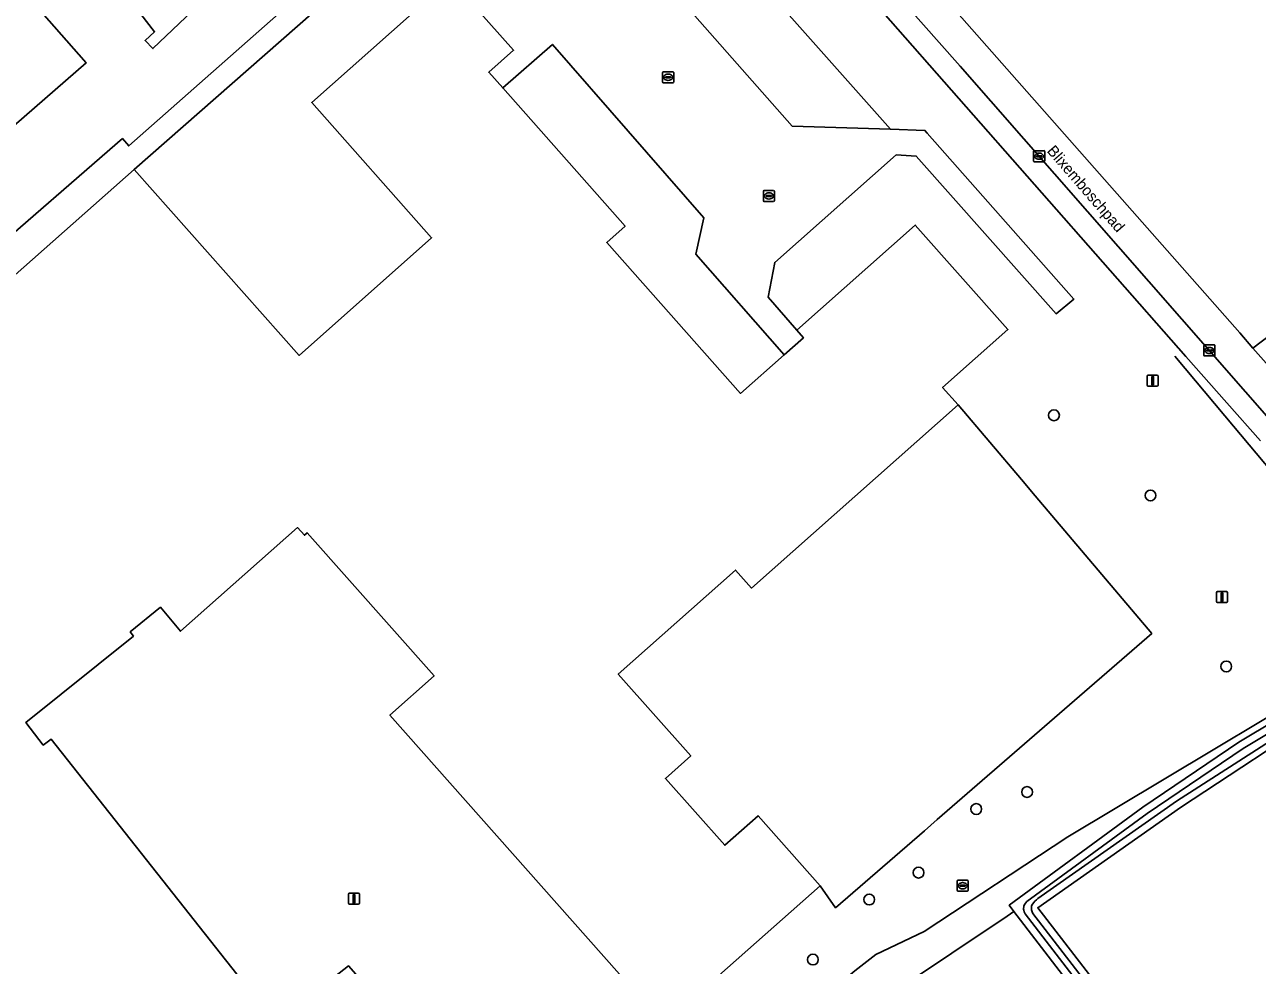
# Model space of a CAD drawing. Extents: x 159451 to 160664, y 388402 to 389723.
# Drawn here: x 159793.8 to 159905.3, y 389005.7 to 389090.8 of the extents above; entities that cross this region are included whole.
import ezdxf

# ---------------------------------------------------------------- set-up
doc = ezdxf.new("R2010")
doc.units = 0
for name, color, linetype in [('IMGEO_Boom', 7, 'Continuous'), ('IMGEO_Erf', 7, 'Continuous'), ('IMGEO_Fietspad_gesloten', 7, 'Continuous'), ('IMGEO_Greppel_droge_sloot', 7, 'Continuous'), ('IMGEO_Groenvoorziening', 7, 'Continuous'), ('IMGEO_Hek', 7, 'Continuous'), ('IMGEO_Kolk', 7, 'Continuous'), ('IMGEO_Lichtmast', 7, 'Continuous'), ('IMGEO_Loofbos', 7, 'Continuous'), ('IMGEO_Oever', 7, 'Continuous'), ('IMGEO_Openbare_ruimte_label', 7, 'Continuous'), ('IMGEO_Pand', 7, 'Continuous'), ('IMGEO_Voetpad_gesloten', 7, 'Continuous'), ('IMGEO_Voetpad_open', 7, 'Continuous')]:
    doc.layers.add(name, color=color, linetype=linetype)

msp = doc.modelspace()

# ---------------------------------------------------------------- linework, layer by layer
at = {"layer": 'IMGEO_Boom'}
for centre in [(159886.9, 389055.46), (159895.63, 389048.21), (159902.48, 389032.75), (159884.47, 389021.4), (159879.87, 389019.86), (159874.65, 389014.11), (159870.19, 389011.68), (159865.1, 389006.25)]:
    msp.add_circle(centre, 0.489, dxfattribs=at)
at = {"layer": 'IMGEO_Erf'}
for points in [[(159811.1, 389205.1), (159812.39, 389206.33), (159879.5, 389250), (159883.29, 389252.48), (159884.66, 389252.42), (159888.52, 389254.99), (159887.08, 389257.25), (159875.98, 389250), (159827.25, 389218.15), (159799.4, 389200.15), (159799.27, 389200.07), (159828.52, 389151.96), (159838.07, 389138), (159844.35, 389130.19), (159903.7, 389062.9), (159904.89, 389061.54), (159920.65, 389073.49)], [(159773.64, 388966.9), (159823.09, 389005.69), (159837.55, 388989.2), (159842.67, 388984.89), (159855.94, 388995.34), (159851.63, 389000.41), (159826.85, 389028.35), (159830.84, 389031.89), (159819.35, 389044.84), (159819.11, 389044.62), (159818.5, 389045.31), (159807.9, 389035.94), (159806.09, 389038.11), (159803.36, 389035.87), (159803.65, 389035.5), (159793.91, 389027.68), (159795.49, 389025.64), (159796.2, 389026.19), (159815.39, 389001.92), (159802.75, 388992.16), (159798.7, 388997.39), (159786.57, 388987.97)]]:
    msp.add_lwpolyline(points, dxfattribs=at)
for points in [[(159785.47, 389097.08), (159790.98, 389090.88), (159790.7, 389090.63), (159792.83, 389088.23), (159781.9, 389078.51), (159785.1, 389074.91), (159799.37, 389087.32), (159788.43, 389099.73)], [(159819.77, 389083.75), (159832.33, 389094.89), (159829.34, 389098.18), (159827.36, 389098.43), (159803.71, 389077.69), (159818.63, 389060.87), (159830.62, 389071.51)], [(159855.25, 389073.32), (159841.54, 389088.99), (159837.05, 389085.05), (159848.12, 389072.56), (159846.46, 389071.08), (159858.56, 389057.43), (159862.49, 389060.92), (159854.52, 389070.02)], [(159865.75, 389012.93), (159867.15, 389010.93), (159875.18, 389017.9), (159876.34, 389018.91), (159895.75, 389035.74), (159885.2, 389048.17), (159883.97, 389049.65), (159878.23, 389056.39), (159859.56, 389039.84), (159858.11, 389041.47), (159847.5, 389032.06), (159854.05, 389024.67), (159851.76, 389022.63), (159857.12, 389016.58), (159860.14, 389019.26)]]:
    msp.add_lwpolyline(points, close=True, dxfattribs=at)
at = {"layer": 'IMGEO_Fietspad_gesloten'}
for points in [[(159917.95, 389046.6), (159909.94, 389055.82), (159904.89, 389061.54), (159903.7, 389062.9), (159844.35, 389130.19), (159838.07, 389138), (159828.52, 389151.96), (159799.27, 389200.07), (159799.4, 389200.15)], [(159796.89, 389198.35), (159802.38, 389189.41), (159812.11, 389173.26), (159824.51, 389152.82), (159827.92, 389147.6), (159831.09, 389142.87), (159835.51, 389136.48), (159838.57, 389132.61), (159846.19, 389123.51), (159867.98, 389098.82), (159878.43, 389087.02), (159907.01, 389054.41), (159915.5, 389044.88), (159924.27, 389033.99), (159926.66, 389035.76), (159926.14, 389036.41), (159917.95, 389046.6)]]:
    msp.add_lwpolyline(points, dxfattribs=at)
at = {"layer": 'IMGEO_Greppel_droge_sloot'}
for points in [[(159913.79, 389031.18), (159904, 389025.32), (159895.33, 389019.47), (159884.45, 389011.49), (159884.33, 389011.36), (159884.2, 389011.16), (159884.17, 389011.07), (159884.15, 389010.81), (159884.17, 389010.72), (159884.22, 389010.56), (159884.29, 389010.4), (159910.13, 388976.78)], [(159911.09, 388976.57), (159884.98, 389010.41), (159884.92, 389010.58), (159884.88, 389010.76), (159884.86, 389010.93), (159884.88, 389011.1), (159884.96, 389011.26), (159885.07, 389011.41), (159885.18, 389011.54), (159885.31, 389011.66), (159885.44, 389011.78), (159897.97, 389020.57), (159911.29, 389029.1)]]:
    msp.add_lwpolyline(points, dxfattribs=at)
at = {"layer": 'IMGEO_Groenvoorziening'}
for points in [[(159905.58, 389053.15), (159902.52, 389056.6), (159898.84, 389060.77), (159850.91, 389115.22)], [(159803.08, 389093.36), (159805.56, 389090.14), (159804.71, 389089.33), (159805.41, 389088.61), (159811.96, 389094.87)], [(159862.95, 389091.64), (159872.11, 389081.32), (159875.23, 389081.22), (159875.44, 389080.98), (159888.71, 389065.96), (159887.09, 389064.64), (159874.45, 389078.9), (159872.63, 389079.01), (159861.65, 389069.28), (159861.06, 389066.14), (159863.64, 389063.15), (159874.36, 389072.66), (159882.73, 389063.22), (159876.82, 389057.98), (159878.23, 389056.39), (159883.97, 389049.65), (159885.2, 389048.17), (159895.75, 389035.74), (159876.34, 389018.91), (159875.18, 389017.9), (159867.15, 389010.93), (159865.75, 389012.93), (159851.63, 389000.41)], [(159857.74, 388993.52), (159882.68, 389010.17), (159883.27, 389010.6), (159882.85, 389011.16), (159894.94, 389020.03), (159903.63, 389025.9), (159913.46, 389031.77)]]:
    msp.add_lwpolyline(points, dxfattribs=at)
at = {"layer": 'IMGEO_Hek'}
for points in [[(159897.84, 389060.79), (159902.35, 389055.41)], [(159902.35, 389055.41), (159918.88, 389035.72), (159888.16, 389017.35), (159875.15, 389008.78), (159870.78, 389006.7), (159868.88, 389005.22), (159856.44, 388994.83)]]:
    msp.add_lwpolyline(points, dxfattribs=at)
at = {"layer": 'IMGEO_Kolk'}
for p, q in [((159851.51, 389085.59), (159851.51, 389086.44)), ((159851.58, 389086.52), (159852.43, 389086.52)), ((159852, 389086.3), (159852.02, 389086.3)), ((159852.51, 389086.44), (159852.51, 389085.59)), ((159852.43, 389085.52), (159851.58, 389085.52)), ((159851.77, 389086.01), (159851.77, 389086.02)), ((159851.81, 389086.06), (159852.21, 389086.06)), ((159852.2, 389085.97), (159851.81, 389085.97)), ((159852.02, 389085.74), (159851.99, 389085.74)), ((159852.25, 389086.02), (159852.25, 389086.01)), ((159885.06, 389078.45), (159885.06, 389079.31)), ((159885.13, 389079.38), (159885.99, 389079.38)), ((159885.32, 389078.87), (159885.32, 389078.89)), ((159885.36, 389078.92), (159885.76, 389078.92)), ((159885.76, 389078.84), (159885.36, 389078.84)), ((159885.55, 389079.16), (159885.57, 389079.16)), ((159885.57, 389078.6), (159885.55, 389078.6)), ((159885.8, 389078.89), (159885.8, 389078.87)), ((159886.06, 389079.31), (159886.06, 389078.45)), ((159885.99, 389078.38), (159885.13, 389078.38)), ((159860.62, 389074.86), (159860.62, 389075.71)), ((159860.7, 389075.79), (159861.55, 389075.79)), ((159860.88, 389075.28), (159860.88, 389075.29)), ((159861.32, 389075.24), (159860.92, 389075.24)), ((159860.93, 389075.33), (159861.32, 389075.33)), ((159861.11, 389075.57), (159861.14, 389075.57)), ((159861.37, 389075.29), (159861.37, 389075.28)), ((159861.62, 389075.71), (159861.62, 389074.86)), ((159861.55, 389074.79), (159860.7, 389074.79)), ((159861.13, 389075.01), (159861.11, 389075.01)), ((159900.45, 389060.89), (159900.45, 389061.75)), ((159900.53, 389061.82), (159901.38, 389061.82)), ((159901.45, 389061.75), (159901.45, 389060.89)), ((159901.38, 389060.82), (159900.53, 389060.82)), ((159900.71, 389061.31), (159900.71, 389061.33)), ((159900.75, 389061.36), (159901.15, 389061.36)), ((159901.15, 389061.28), (159900.75, 389061.28)), ((159900.94, 389061.6), (159900.97, 389061.6)), ((159900.96, 389061.04), (159900.94, 389061.04)), ((159901.2, 389061.33), (159901.2, 389061.31)), ((159878.15, 389012.51), (159878.15, 389013.36)), ((159878.22, 389013.44), (159879.07, 389013.44)), ((159878.41, 389012.93), (159878.41, 389012.94)), ((159878.45, 389012.98), (159878.85, 389012.98)), ((159878.84, 389012.89), (159878.45, 389012.89)), ((159878.64, 389013.21), (159878.66, 389013.21)), ((159878.89, 389012.94), (159878.89, 389012.93)), ((159879.15, 389013.36), (159879.15, 389012.51)), ((159879.07, 389012.43), (159878.22, 389012.43)), ((159878.66, 389012.66), (159878.63, 389012.66))]:
    msp.add_line(p, q, dxfattribs=at)
for points in [[(159851.51, 389085.59), (159851.51, 389086.44)], [(159851.58, 389086.52), (159852.43, 389086.52)], [(159852.51, 389086.44), (159852.51, 389085.59)], [(159852.43, 389085.52), (159851.58, 389085.52)], [(159885.06, 389078.45), (159885.06, 389079.31)], [(159885.13, 389079.38), (159885.99, 389079.38)], [(159886.06, 389079.31), (159886.06, 389078.45)], [(159885.99, 389078.38), (159885.13, 389078.38)], [(159860.62, 389074.86), (159860.62, 389075.71)], [(159860.7, 389075.79), (159861.55, 389075.79)], [(159861.62, 389075.71), (159861.62, 389074.86)], [(159861.55, 389074.79), (159860.7, 389074.79)], [(159900.45, 389060.89), (159900.45, 389061.75)], [(159900.53, 389061.82), (159901.38, 389061.82)], [(159901.45, 389061.75), (159901.45, 389060.89)], [(159901.38, 389060.82), (159900.53, 389060.82)], [(159878.15, 389012.51), (159878.15, 389013.36)], [(159878.22, 389013.44), (159879.07, 389013.44)], [(159879.15, 389013.36), (159879.15, 389012.51)], [(159879.07, 389012.43), (159878.22, 389012.43)]]:
    msp.add_lwpolyline(points, dxfattribs=at)
for centre, radius, start, end in [((159851.58, 389086.44), 0.0765, 91.552, 178.448), ((159851.58, 389086.44), 0.0765, 91.552, 178.448), ((159852.43, 389086.44), 0.0765, 1.552, 88.448), ((159852.43, 389086.44), 0.0765, 1.552, 88.448), ((159851.58, 389085.59), 0.0765, 181.552, 268.448), ((159851.58, 389085.59), 0.0765, 181.552, 268.448), ((159851.81, 389086.02), 0.0403, 85.8775, 175.7526), ((159851.8, 389086.01), 0.0366, 178.938, 274.7102), ((159852.21, 389086.02), 0.043, 264.8664, 352.4533), ((159852.21, 389086.02), 0.0386, 1.7309, 96.639), ((159852.43, 389085.59), 0.0765, 271.552, 358.448), ((159852.43, 389085.59), 0.0765, 271.552, 358.448), ((159885.14, 389079.31), 0.0765, 91.552, 178.448), ((159885.14, 389079.31), 0.0765, 91.552, 178.448), ((159885.36, 389078.88), 0.0403, 85.8775, 175.7526), ((159885.36, 389078.87), 0.0366, 178.938, 274.7102), ((159885.76, 389078.89), 0.0386, 1.7309, 96.639), ((159885.76, 389078.88), 0.043, 264.8664, 352.4533), ((159885.98, 389079.31), 0.0765, 1.552, 88.448), ((159885.98, 389079.31), 0.0765, 1.552, 88.448), ((159885.14, 389078.46), 0.0765, 181.552, 268.448), ((159885.14, 389078.46), 0.0765, 181.552, 268.448), ((159885.98, 389078.46), 0.0765, 271.552, 358.448), ((159885.98, 389078.46), 0.0765, 271.552, 358.448), ((159860.7, 389075.71), 0.0765, 91.552, 178.448), ((159860.7, 389075.71), 0.0765, 91.552, 178.448), ((159860.92, 389075.29), 0.0403, 85.8775, 175.7526), ((159860.92, 389075.28), 0.0366, 178.938, 274.7102), ((159861.33, 389075.29), 0.0386, 1.7309, 96.639), ((159861.32, 389075.29), 0.043, 264.8664, 352.4533), ((159861.55, 389075.71), 0.0765, 1.552, 88.448), ((159861.55, 389075.71), 0.0765, 1.552, 88.448), ((159860.7, 389074.86), 0.0765, 181.552, 268.448), ((159860.7, 389074.86), 0.0765, 181.552, 268.448), ((159861.55, 389074.86), 0.0765, 271.552, 358.448), ((159861.55, 389074.86), 0.0765, 271.552, 358.448), ((159900.53, 389061.75), 0.0765, 91.552, 178.448), ((159900.53, 389061.75), 0.0765, 91.552, 178.448), ((159901.38, 389061.75), 0.0765, 1.552, 88.448), ((159901.38, 389061.75), 0.0765, 1.552, 88.448), ((159900.53, 389060.9), 0.0765, 181.552, 268.448), ((159900.53, 389060.9), 0.0765, 181.552, 268.448), ((159900.75, 389061.32), 0.0403, 85.8775, 175.7526), ((159900.75, 389061.31), 0.0366, 178.938, 274.7102), ((159901.16, 389061.33), 0.0386, 1.7309, 96.639), ((159901.15, 389061.32), 0.043, 264.8664, 352.4533), ((159901.38, 389060.9), 0.0765, 271.552, 358.448), ((159901.38, 389060.9), 0.0765, 271.552, 358.448), ((159878.22, 389013.36), 0.0765, 91.552, 178.448), ((159878.22, 389013.36), 0.0765, 91.552, 178.448), ((159878.45, 389012.94), 0.0403, 85.8775, 175.7526), ((159878.44, 389012.93), 0.0366, 178.938, 274.7102), ((159878.85, 389012.93), 0.043, 264.8664, 352.4533), ((159878.85, 389012.94), 0.0386, 1.7309, 96.639), ((159879.07, 389013.36), 0.0765, 1.552, 88.448), ((159879.07, 389013.36), 0.0765, 1.552, 88.448), ((159878.22, 389012.51), 0.0765, 181.552, 268.448), ((159878.22, 389012.51), 0.0765, 181.552, 268.448), ((159879.07, 389012.51), 0.0765, 271.552, 358.448), ((159879.07, 389012.51), 0.0765, 271.552, 358.448)]:
    msp.add_arc(centre, radius, start, end, dxfattribs=at)
for centre, major_axis, ratio, start_param, end_param in [((159851.99, 389086.02), (-0.387, 0.002), 0.722429, 4.712389, 7.853982), ((159852.02, 389086.02), (-0.39, 0.002), 0.717154, 1.570796, 4.712389), ((159885.55, 389078.88), (-0.387, 0.002), 0.722429, 4.712389, 7.853982), ((159885.57, 389078.88), (-0.39, 0.002), 0.717154, 1.570796, 4.712389), ((159861.11, 389075.29), (-0.387, 0.002), 0.722429, 4.712389, 7.853982), ((159861.13, 389075.29), (-0.39, 0.002), 0.717154, 1.570796, 4.712389), ((159900.94, 389061.32), (-0.387, 0.002), 0.722429, 4.712389, 7.853982), ((159900.96, 389061.32), (-0.39, 0.002), 0.717154, 1.570796, 4.712389), ((159878.63, 389012.93), (-0.387, 0.002), 0.722429, 4.712389, 7.853982), ((159878.66, 389012.93), (-0.39, 0.002), 0.717154, 1.570796, 4.712389)]:
    msp.add_ellipse(centre, major_axis=major_axis, ratio=ratio, start_param=start_param, end_param=end_param, dxfattribs=at)
at = {"layer": 'IMGEO_Lichtmast'}
for p, q in [((159895.32, 389058.19), (159895.32, 389058.99)), ((159895.32, 389058.99), (159895.32, 389058.19)), ((159895.42, 389059.09), (159896.21, 389059.09)), ((159896.21, 389059.09), (159895.42, 389059.09)), ((159896.31, 389058.99), (159896.31, 389058.19)), ((159896.31, 389058.19), (159896.31, 389058.99)), ((159896.21, 389058.09), (159895.42, 389058.09)), ((159895.42, 389058.09), (159896.21, 389058.09)), ((159901.7, 389039.52), (159902.49, 389039.52)), ((159902.49, 389039.52), (159901.7, 389039.52)), ((159901.6, 389038.62), (159901.6, 389039.42)), ((159901.6, 389039.42), (159901.6, 389038.62)), ((159902.49, 389038.52), (159901.7, 389038.52)), ((159901.7, 389038.52), (159902.49, 389038.52)), ((159902.59, 389039.42), (159902.59, 389038.62)), ((159902.59, 389038.62), (159902.59, 389039.42)), ((159823.09, 389011.36), (159823.09, 389012.15)), ((159823.09, 389012.15), (159823.09, 389011.36)), ((159823.19, 389012.25), (159823.98, 389012.25)), ((159823.98, 389012.25), (159823.19, 389012.25)), ((159824.08, 389012.15), (159824.08, 389011.36)), ((159824.08, 389011.36), (159824.08, 389012.15)), ((159823.98, 389011.26), (159823.19, 389011.26)), ((159823.19, 389011.26), (159823.98, 389011.26))]:
    msp.add_line(p, q, dxfattribs=at)
for points in [[(159895.74, 389058.97), (159895.89, 389058.97), (159895.89, 389058.22), (159895.74, 389058.22), (159895.74, 389058.97)], [(159902.02, 389039.4), (159902.17, 389039.4), (159902.17, 389038.65), (159902.02, 389038.65), (159902.02, 389039.4)], [(159823.51, 389012.13), (159823.66, 389012.13), (159823.66, 389011.38), (159823.51, 389011.38), (159823.51, 389012.13)]]:
    msp.add_lwpolyline(points, dxfattribs=at)
for centre, start, end in [((159895.42, 389058.99), 90, 180), ((159895.42, 389058.99), 90, 180), ((159896.21, 389058.99), 0, 90), ((159896.21, 389058.99), 360, 90), ((159895.42, 389058.19), 180, 270), ((159895.42, 389058.19), 180, 270), ((159896.21, 389058.19), 270, 0), ((159896.21, 389058.19), 270, 0), ((159901.7, 389039.42), 90, 180), ((159901.7, 389039.42), 90, 180), ((159902.49, 389039.42), 0, 90), ((159902.49, 389039.42), 360, 90), ((159901.7, 389038.62), 180, 270), ((159901.7, 389038.62), 180, 270), ((159902.49, 389038.62), 270, 0), ((159902.49, 389038.62), 270, 0), ((159823.19, 389012.15), 90, 180), ((159823.19, 389012.15), 90, 180), ((159823.98, 389012.15), 0, 90), ((159823.98, 389012.15), 360, 90), ((159823.19, 389011.36), 180, 270), ((159823.19, 389011.36), 180, 270), ((159823.98, 389011.36), 270, 0), ((159823.98, 389011.36), 270, 0)]:
    msp.add_arc(centre, 0.1, start, end, dxfattribs=at)
at = {"layer": 'IMGEO_Loofbos'}
for points in [[(159920.65, 389073.49), (159904.89, 389061.54), (159909.94, 389055.82), (159917.95, 389046.6), (159926.14, 389036.41), (159927.4, 389037.07), (159926.3, 389038.59), (159953.01, 389052.15), (159934.26, 389060.68), (159927.6, 389062.99), (159922.93, 389065.72), (159922.12, 389066.86)], [(159909.98, 388975.85), (159883.27, 389010.6), (159882.68, 389010.17), (159857.74, 388993.52), (159843.47, 388983.99), (159844.49, 388982.83), (159845, 388982.26), (159846.64, 388980.41), (159849.85, 388974.79), (159878.23, 388937.88), (159908.99, 388959.5), (159917.43, 388966.17), (159910.9, 388974.66), (159896.25, 388964.24)]]:
    msp.add_lwpolyline(points, dxfattribs=at)
msp.add_lwpolyline([(159925.88, 389027.51), (159922.02, 389034.23), (159911.64, 389028.75), (159898.35, 389020.01), (159885.43, 389010.94), (159919.2, 388967.18), (159936.66, 388977.13), (159947.41, 388982.61), (159956.5, 388986.85), (159956.11, 388989.07)], close=True, dxfattribs=at)
at = {"layer": 'IMGEO_Oever'}
for points in [[(159913.46, 389031.77), (159903.63, 389025.9), (159894.94, 389020.03), (159882.85, 389011.16), (159883.27, 389010.6), (159909.98, 388975.85)], [(159910.13, 388976.78), (159884.29, 389010.4), (159884.22, 389010.56), (159884.17, 389010.72), (159884.15, 389010.81), (159884.17, 389011.07), (159884.2, 389011.16), (159884.33, 389011.36), (159884.45, 389011.49), (159895.33, 389019.47), (159904, 389025.32), (159913.79, 389031.18)], [(159911.29, 389029.1), (159897.97, 389020.57), (159885.44, 389011.78), (159885.31, 389011.66), (159885.18, 389011.54), (159885.07, 389011.41), (159884.96, 389011.26), (159884.88, 389011.1), (159884.86, 389010.93), (159884.88, 389010.76), (159884.92, 389010.58), (159884.98, 389010.41), (159911.09, 388976.57)], [(159885.43, 389010.94), (159898.35, 389020.01), (159911.64, 389028.75)], [(159919.2, 388967.18), (159885.43, 389010.94)]]:
    msp.add_lwpolyline(points, dxfattribs=at)
at = {"layer": 'IMGEO_Pand'}
msp.add_lwpolyline([(159815.39, 389001.92), (159796.2, 389026.19), (159795.49, 389025.64), (159793.91, 389027.68), (159803.65, 389035.5), (159803.36, 389035.87), (159806.09, 389038.11), (159807.9, 389035.94), (159818.5, 389045.31), (159819.11, 389044.62), (159819.35, 389044.84), (159830.84, 389031.89), (159826.85, 389028.35), (159851.63, 389000.41), (159865.75, 389012.93), (159860.14, 389019.26), (159857.12, 389016.58), (159851.76, 389022.63), (159854.05, 389024.67), (159847.5, 389032.06), (159858.11, 389041.47), (159859.56, 389039.84), (159878.23, 389056.39), (159876.82, 389057.98), (159882.73, 389063.22), (159874.36, 389072.66), (159863.64, 389063.15), (159864.24, 389062.47), (159862.49, 389060.92), (159858.56, 389057.43), (159846.46, 389071.08), (159848.12, 389072.56), (159837.05, 389085.05), (159835.79, 389086.47), (159838.03, 389088.46), (159832.33, 389094.89), (159819.77, 389083.75), (159830.62, 389071.51), (159818.63, 389060.87), (159803.71, 389077.69), (159791.91, 389067.23)], dxfattribs=at)
at = {"layer": 'IMGEO_Voetpad_gesloten'}
for points in [[(159788.43, 389099.73), (159799.37, 389087.32), (159785.1, 389074.91), (159789.94, 389069.45), (159802.65, 389080.47), (159803.23, 389079.81), (159823.67, 389097.87)], [(159804.71, 389089.33), (159805.56, 389090.14), (159803.08, 389093.36), (159801.42, 389095.52)], [(159811.96, 389094.87), (159805.41, 389088.61), (159804.71, 389089.33)]]:
    msp.add_lwpolyline(points, dxfattribs=at)
at = {"layer": 'IMGEO_Voetpad_open'}
for points in [[(159850.91, 389115.22), (159898.84, 389060.77), (159902.52, 389056.6), (159905.58, 389053.15)], [(159907.01, 389054.41), (159878.43, 389087.02), (159867.98, 389098.82)], [(159823.67, 389097.87), (159803.23, 389079.81), (159802.65, 389080.47), (159789.94, 389069.45), (159791.91, 389067.23), (159803.71, 389077.69), (159827.36, 389098.43)], [(159832.33, 389094.89), (159838.03, 389088.46), (159835.79, 389086.47), (159837.05, 389085.05), (159841.54, 389088.99), (159855.25, 389073.32), (159854.52, 389070.02), (159862.49, 389060.92), (159864.24, 389062.47), (159863.64, 389063.15), (159861.06, 389066.14), (159861.65, 389069.28), (159872.63, 389079.01), (159874.45, 389078.9), (159887.09, 389064.64), (159888.71, 389065.96), (159875.44, 389080.98), (159875.23, 389081.22), (159872.11, 389081.32), (159863.23, 389081.61), (159850.81, 389095.71)]]:
    msp.add_lwpolyline(points, dxfattribs=at)
msp.add_lwpolyline([(159851.22, 389096.07), (159850.81, 389095.71), (159863.23, 389081.61), (159872.11, 389081.32), (159862.95, 389091.64), (159863.63, 389092.24), (159861.18, 389094.99), (159860.58, 389094.46), (159855.65, 389100)], close=True, dxfattribs=at)

# ---------------------------------------------------------------- texts
at = {"layer": 'IMGEO_Openbare_ruimte_label'}
msp.add_text('Blixemboschpad', height=1, rotation=310.8624, dxfattribs=at).set_placement((159886.21, 389079.33))

doc.saveas('drawing.dxf')
